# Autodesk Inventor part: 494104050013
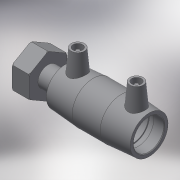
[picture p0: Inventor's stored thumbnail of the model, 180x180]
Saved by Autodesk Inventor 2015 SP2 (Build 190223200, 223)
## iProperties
Created: 2017-06
Part Number: 494104050013
Material: Generic
Description: PLASSON FEMALE FREE NUT TRANSITION COUPLER 50- 1¼''
Document SubType Name: Modeling
Designer: KIM
Mass: 55.0731 g
Surface Area: 148.067 cm^2
Volume: 55.0731 cm^3
Density: 1 g/cm^3
Appearance: Default
Author: KIM
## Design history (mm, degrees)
derived "494104.ipt"
feature "Solid1::494104.ipt"
tag "TaggingFeature1"
body "Solid1"
other parameters: "d2" = 67, "d3" = 49, "d4" = 33.33333, "d5" = 60.3, "d6" = 47.5, "d8" = 168 deg, "d10" = 19.6, "d11" = 6.53333, "d29" = 52, "d30" = 14, "d31" = 35, "d34" = 5 deg, "d41" = 4, "d42" = 14, "d43" = 0, "d48" = 3, "d49" = 0, "d55" = 36, "d57" = 23, "d80" = 1, "d83" = 18, "d84" = 11.88, "d85" = 1.188, "d86" = 31.1616, "d87" = 38.952, "d88" = 58.428, "d89" = 67, "d90" = 1.16856, "d94" = 0, "d95" = 1.188, "d96" = 27.2664, "L_" = 136, "L_1" = 49, "D_1" = 67, "A_" = 52, "d_2" = 12, "L_2" = 36, "D_" = 23, "G_" = 38.952
